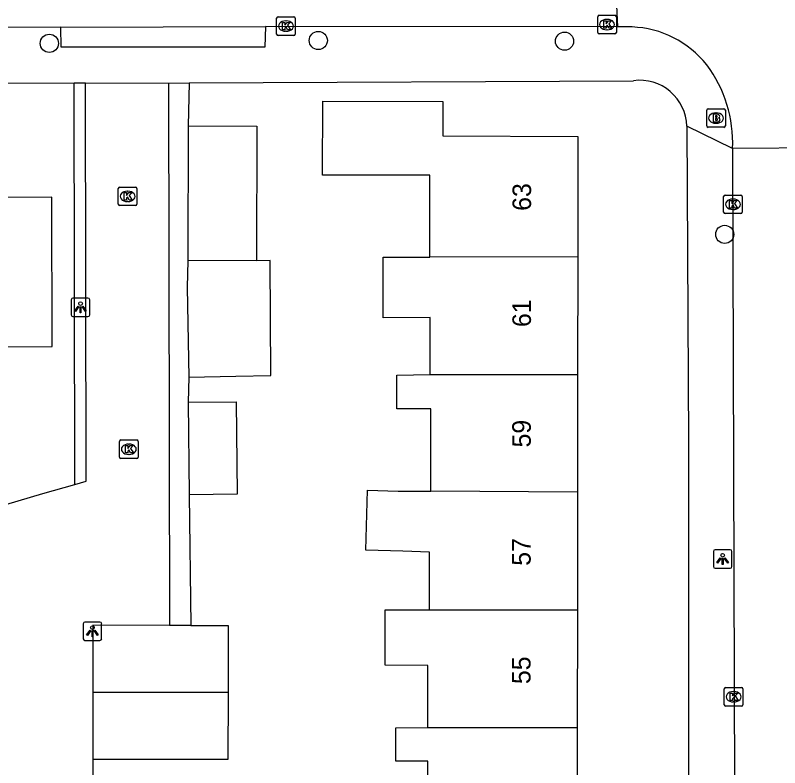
# Model space of a CAD drawing. Extents: x 160732 to 162105, y 387428 to 388479.
# Drawn here: x 161117.3 to 161158.48, y 388190.26 to 388230.78 of the extents above; entities that cross this region are included whole.
import ezdxf

# ---------------------------------------------------------------- set-up
doc = ezdxf.new("R2010")
doc.units = 0
for name, color, linetype in [('IMGEO_Boom', 7, 'Continuous'), ('IMGEO_Brandkraan', 7, 'Continuous'), ('IMGEO_Kolk', 7, 'Continuous'), ('IMGEO_Lichtpunt', 7, 'Continuous'), ('IMGEO_Muur', 7, 'Continuous'), ('IMGEO_Pand', 7, 'Continuous'), ('IMGEO_Pand_nummerreeks', 7, 'Continuous'), ('IMGEO_Rijbaan_lokaal_open', 7, 'Continuous'), ('IMGEO_Voetpad_open', 7, 'Continuous')]:
    doc.layers.add(name, color=color, linetype=linetype)

msp = doc.modelspace()

# ---------------------------------------------------------------- linework, layer by layer
at = {"layer": 'IMGEO_Boom'}
for centre in [(161119.136, 388229.271), (161133.623, 388229.425), (161146.891, 388229.388), (161155.522, 388218.983)]:
    msp.add_circle(centre, 0.489, dxfattribs=at)
at = {"layer": 'IMGEO_Brandkraan'}
for p, q in [((161154.554, 388224.823), (161154.554, 388225.675)), ((161154.629, 388225.749), (161155.481, 388225.749)), ((161155.555, 388225.675), (161155.555, 388224.823)), ((161155.042, 388225.529), (161155.067, 388225.529)), ((161155.065, 388224.969), (161155.04, 388224.969)), ((161155.481, 388224.749), (161154.629, 388224.749))]:
    msp.add_line(p, q, dxfattribs=at)
for points in [[(161154.554, 388224.823), (161154.554, 388225.675)], [(161154.629, 388225.749), (161155.481, 388225.749)], [(161155.555, 388225.675), (161155.555, 388224.823)], [(161154.902, 388225.449), (161154.902, 388225.049), (161155.115, 388225.049)], [(161155.133, 388225.449), (161154.902, 388225.449)], [(161155.081, 388225.368), (161155.027, 388225.368), (161155.027, 388225.292)], [(161155.027, 388225.292), (161155.08, 388225.292)], [(161155.089, 388225.216), (161155.027, 388225.216), (161155.027, 388225.135)], [(161155.027, 388225.135), (161155.089, 388225.135)], [(161155.481, 388224.749), (161154.629, 388224.749)]]:
    msp.add_lwpolyline(points, dxfattribs=at)
for centre, radius, start, end in [((161154.631, 388225.673), 0.0765, 91.552, 178.448), ((161154.631, 388225.673), 0.0765, 91.552, 178.448), ((161155.479, 388225.673), 0.0765, 1.552, 88.448), ((161155.479, 388225.673), 0.0765, 1.552, 88.448), ((161155.082, 388225.33), 0.0379, 267.8285, 90.9355), ((161155.09, 388225.175), 0.0404, 269.8759, 90.5077), ((161155.137, 388225.304), 0.145, 59.4692, 91.5367), ((161155.162, 388225.351), 0.0922, 285.5137, 58.1501), ((161155.167, 388225.159), 0.105, 301.3115, 78.989), ((161154.631, 388224.825), 0.0765, 181.552, 268.448), ((161154.631, 388224.825), 0.0765, 181.552, 268.448), ((161155.121, 388225.3), 0.251, 268.6676, 293.5347), ((161155.479, 388224.825), 0.0765, 271.552, 358.448), ((161155.479, 388224.825), 0.0765, 271.552, 358.448)]:
    msp.add_arc(centre, radius, start, end, dxfattribs=at)
for centre, major_axis, ratio, start_param, end_param in [((161155.041, 388225.249), (-0.387, 0.002), 0.722429, 4.712389, 7.853982), ((161155.066, 388225.249), (-0.39, 0.002), 0.717154, 1.570796, 4.712389)]:
    msp.add_ellipse(centre, major_axis=major_axis, ratio=ratio, start_param=start_param, end_param=end_param, dxfattribs=at)
at = {"layer": 'IMGEO_Kolk'}
for p, q in [((161131.38, 388229.773), (161131.38, 388230.625)), ((161131.455, 388230.699), (161132.307, 388230.699)), ((161132.381, 388230.625), (161132.381, 388229.773)), ((161148.682, 388229.856), (161148.682, 388230.708)), ((161148.757, 388230.782), (161149.609, 388230.782)), ((161149.17, 388230.562), (161149.195, 388230.562)), ((161149.683, 388230.708), (161149.683, 388229.856)), ((161131.868, 388230.479), (161131.893, 388230.479)), ((161131.891, 388229.919), (161131.866, 388229.919)), ((161149.609, 388229.782), (161148.757, 388229.782)), ((161149.193, 388230.002), (161149.168, 388230.002)), ((161132.307, 388229.699), (161131.455, 388229.699)), ((161122.926, 388221.531), (161123.778, 388221.531)), ((161122.851, 388220.605), (161122.851, 388221.457)), ((161123.339, 388221.311), (161123.364, 388221.311)), ((161123.852, 388221.457), (161123.852, 388220.605)), ((161155.537, 388221.103), (161156.389, 388221.103)), ((161123.362, 388220.751), (161123.337, 388220.751)), ((161155.462, 388220.177), (161155.462, 388221.029)), ((161155.95, 388220.883), (161155.975, 388220.883)), ((161156.463, 388221.029), (161156.463, 388220.177)), ((161123.778, 388220.531), (161122.926, 388220.531)), ((161155.973, 388220.323), (161155.948, 388220.323)), ((161156.389, 388220.103), (161155.537, 388220.103)), ((161122.992, 388207.911), (161123.844, 388207.911)), ((161122.917, 388206.985), (161122.917, 388207.837)), ((161123.405, 388207.691), (161123.43, 388207.691)), ((161123.918, 388207.837), (161123.918, 388206.985)), ((161123.428, 388207.131), (161123.403, 388207.131)), ((161123.844, 388206.911), (161122.992, 388206.911)), ((161155.497, 388193.654), (161155.497, 388194.506)), ((161155.572, 388194.58), (161156.424, 388194.58)), ((161155.985, 388194.36), (161156.01, 388194.36)), ((161156.498, 388194.506), (161156.498, 388193.654)), ((161156.424, 388193.58), (161155.572, 388193.58)), ((161156.008, 388193.8), (161155.983, 388193.8))]:
    msp.add_line(p, q, dxfattribs=at)
for points in [[(161131.38, 388229.773), (161131.38, 388230.625)], [(161131.455, 388230.699), (161132.307, 388230.699)], [(161132.381, 388230.625), (161132.381, 388229.773)], [(161148.682, 388229.856), (161148.682, 388230.708)], [(161148.757, 388230.782), (161149.609, 388230.782)], [(161149.683, 388230.708), (161149.683, 388229.856)], [(161131.701, 388230.399), (161131.824, 388230.399), (161131.824, 388230.248), (161131.954, 388230.399), (161132.118, 388230.399), (161131.972, 388230.248), (161132.125, 388229.999), (161131.973, 388229.999), (161131.888, 388230.163), (161131.824, 388230.096), (161131.824, 388229.999), (161131.701, 388229.999), (161131.701, 388230.399)], [(161149.003, 388230.482), (161149.126, 388230.482), (161149.126, 388230.331), (161149.256, 388230.482), (161149.42, 388230.482), (161149.274, 388230.331), (161149.427, 388230.082), (161149.275, 388230.082), (161149.19, 388230.246), (161149.126, 388230.179), (161149.126, 388230.082), (161149.003, 388230.082), (161149.003, 388230.482)], [(161149.609, 388229.782), (161148.757, 388229.782)], [(161132.307, 388229.699), (161131.455, 388229.699)], [(161122.926, 388221.531), (161123.778, 388221.531)], [(161122.851, 388220.605), (161122.851, 388221.457)], [(161123.172, 388221.231), (161123.295, 388221.231), (161123.295, 388221.08), (161123.425, 388221.231), (161123.589, 388221.231), (161123.443, 388221.08), (161123.596, 388220.831), (161123.444, 388220.831), (161123.359, 388220.995), (161123.295, 388220.928), (161123.295, 388220.831), (161123.172, 388220.831), (161123.172, 388221.231)], [(161123.852, 388221.457), (161123.852, 388220.605)], [(161155.537, 388221.103), (161156.389, 388221.103)], [(161155.462, 388220.177), (161155.462, 388221.029)], [(161155.783, 388220.803), (161155.906, 388220.803), (161155.906, 388220.652), (161156.036, 388220.803), (161156.2, 388220.803), (161156.054, 388220.652), (161156.207, 388220.403), (161156.055, 388220.403), (161155.97, 388220.567), (161155.906, 388220.5), (161155.906, 388220.403), (161155.783, 388220.403), (161155.783, 388220.803)], [(161156.463, 388221.029), (161156.463, 388220.177)], [(161123.778, 388220.531), (161122.926, 388220.531)], [(161156.389, 388220.103), (161155.537, 388220.103)], [(161122.992, 388207.911), (161123.844, 388207.911)], [(161122.917, 388206.985), (161122.917, 388207.837)], [(161123.238, 388207.611), (161123.361, 388207.611), (161123.361, 388207.46), (161123.491, 388207.611), (161123.655, 388207.611), (161123.509, 388207.46), (161123.662, 388207.211), (161123.51, 388207.211), (161123.425, 388207.375), (161123.361, 388207.308), (161123.361, 388207.211), (161123.238, 388207.211), (161123.238, 388207.611)], [(161123.918, 388207.837), (161123.918, 388206.985)], [(161123.844, 388206.911), (161122.992, 388206.911)], [(161155.497, 388193.654), (161155.497, 388194.506)], [(161155.572, 388194.58), (161156.424, 388194.58)], [(161156.498, 388194.506), (161156.498, 388193.654)], [(161155.818, 388194.28), (161155.941, 388194.28), (161155.941, 388194.129), (161156.071, 388194.28), (161156.235, 388194.28), (161156.089, 388194.129), (161156.242, 388193.88), (161156.09, 388193.88), (161156.005, 388194.044), (161155.941, 388193.977), (161155.941, 388193.88), (161155.818, 388193.88), (161155.818, 388194.28)], [(161156.424, 388193.58), (161155.572, 388193.58)]]:
    msp.add_lwpolyline(points, dxfattribs=at)
for centre, start, end in [((161131.457, 388230.623), 91.552, 178.448), ((161131.457, 388230.623), 91.552, 178.448), ((161132.305, 388230.623), 1.552, 88.448), ((161132.305, 388230.623), 1.552, 88.448), ((161148.759, 388230.706), 91.552, 178.448), ((161148.759, 388230.706), 91.552, 178.448), ((161149.607, 388230.706), 1.552, 88.448), ((161149.607, 388230.706), 1.552, 88.448), ((161131.457, 388229.775), 181.552, 268.448), ((161131.457, 388229.775), 181.552, 268.448), ((161132.305, 388229.775), 271.552, 358.448), ((161132.305, 388229.775), 271.552, 358.448), ((161148.759, 388229.858), 181.552, 268.448), ((161148.759, 388229.858), 181.552, 268.448), ((161149.607, 388229.858), 271.552, 358.448), ((161149.607, 388229.858), 271.552, 358.448), ((161122.928, 388221.455), 91.552, 178.448), ((161122.928, 388221.455), 91.552, 178.448), ((161123.776, 388221.455), 1.552, 88.448), ((161123.776, 388221.455), 1.552, 88.448), ((161155.539, 388221.027), 91.552, 178.448), ((161155.539, 388221.027), 91.552, 178.448), ((161156.387, 388221.027), 1.552, 88.448), ((161156.387, 388221.027), 1.552, 88.448), ((161122.928, 388220.607), 181.552, 268.448), ((161122.928, 388220.607), 181.552, 268.448), ((161123.776, 388220.607), 271.552, 358.448), ((161123.776, 388220.607), 271.552, 358.448), ((161155.539, 388220.179), 181.552, 268.448), ((161155.539, 388220.179), 181.552, 268.448), ((161156.387, 388220.179), 271.552, 358.448), ((161156.387, 388220.179), 271.552, 358.448), ((161122.994, 388207.835), 91.552, 178.448), ((161122.994, 388207.835), 91.552, 178.448), ((161123.842, 388207.835), 1.552, 88.448), ((161123.842, 388207.835), 1.552, 88.448), ((161122.994, 388206.987), 181.552, 268.448), ((161122.994, 388206.987), 181.552, 268.448), ((161123.842, 388206.987), 271.552, 358.448), ((161123.842, 388206.987), 271.552, 358.448), ((161155.574, 388194.504), 91.552, 178.448), ((161155.574, 388194.504), 91.552, 178.448), ((161156.422, 388194.504), 1.552, 88.448), ((161156.422, 388194.504), 1.552, 88.448), ((161155.574, 388193.656), 181.552, 268.448), ((161155.574, 388193.656), 181.552, 268.448), ((161156.422, 388193.656), 271.552, 358.448), ((161156.422, 388193.656), 271.552, 358.448)]:
    msp.add_arc(centre, 0.0765, start, end, dxfattribs=at)
for centre, major_axis, ratio, start_param, end_param in [((161149.169, 388230.282), (-0.387, 0.002), 0.722429, 4.712389, 7.853982), ((161149.194, 388230.282), (-0.39, 0.002), 0.717154, 1.570796, 4.712389), ((161131.867, 388230.199), (-0.387, 0.002), 0.722429, 4.712389, 7.853982), ((161131.892, 388230.199), (-0.39, 0.002), 0.717154, 1.570796, 4.712389), ((161123.338, 388221.031), (-0.387, 0.002), 0.722429, 4.712389, 7.853982), ((161123.363, 388221.031), (-0.39, 0.002), 0.717154, 1.570796, 4.712389), ((161155.949, 388220.603), (-0.387, 0.002), 0.722429, 4.712389, 7.853982), ((161155.974, 388220.603), (-0.39, 0.002), 0.717154, 1.570796, 4.712389), ((161123.404, 388207.411), (-0.387, 0.002), 0.722429, 4.712389, 7.853982), ((161123.429, 388207.411), (-0.39, 0.002), 0.717154, 1.570796, 4.712389), ((161155.984, 388194.08), (-0.387, 0.002), 0.722429, 4.712389, 7.853982), ((161156.009, 388194.08), (-0.39, 0.002), 0.717154, 1.570796, 4.712389)]:
    msp.add_ellipse(centre, major_axis=major_axis, ratio=ratio, start_param=start_param, end_param=end_param, dxfattribs=at)
at = {"layer": 'IMGEO_Lichtpunt'}
for p, q in [((161120.316, 388215.461), (161120.316, 388214.654)), ((161120.316, 388215.461), (161120.316, 388214.654)), ((161121.218, 388215.556), (161120.41, 388215.556)), ((161121.218, 388215.556), (161120.41, 388215.556)), ((161121.312, 388214.654), (161121.312, 388215.461)), ((161121.312, 388214.654), (161121.312, 388215.461)), ((161120.41, 388214.56), (161121.218, 388214.56)), ((161120.41, 388214.56), (161121.218, 388214.56)), ((161154.91, 388201.905), (161154.91, 388201.098)), ((161154.91, 388201.905), (161154.91, 388201.098)), ((161155.812, 388202), (161155.004, 388202)), ((161155.812, 388202), (161155.004, 388202)), ((161155.906, 388201.098), (161155.906, 388201.905)), ((161155.906, 388201.098), (161155.906, 388201.905)), ((161155.004, 388201.004), (161155.812, 388201.004)), ((161155.004, 388201.004), (161155.812, 388201.004)), ((161120.958, 388198.013), (161120.958, 388197.206)), ((161120.958, 388198.013), (161120.958, 388197.206)), ((161121.86, 388198.108), (161121.052, 388198.108)), ((161121.86, 388198.108), (161121.052, 388198.108)), ((161121.954, 388197.206), (161121.954, 388198.013)), ((161121.954, 388197.206), (161121.954, 388198.013)), ((161121.052, 388197.112), (161121.86, 388197.112)), ((161121.052, 388197.112), (161121.86, 388197.112))]:
    msp.add_line(p, q, dxfattribs=at)
for points in [[(161120.69, 388215.125), (161120.729, 388215.097), (161120.541, 388214.835), (161120.503, 388214.862), (161120.69, 388215.125)], [(161120.792, 388215.077), (161120.839, 388215.077), (161120.839, 388214.755), (161120.792, 388214.755), (161120.792, 388215.077)], [(161120.902, 388215.097), (161120.94, 388215.124), (161121.127, 388214.862), (161121.088, 388214.834), (161120.902, 388215.097)], [(161155.284, 388201.569), (161155.323, 388201.541), (161155.135, 388201.279), (161155.097, 388201.306), (161155.284, 388201.569)], [(161155.386, 388201.521), (161155.433, 388201.521), (161155.433, 388201.199), (161155.386, 388201.199), (161155.386, 388201.521)], [(161155.496, 388201.541), (161155.534, 388201.568), (161155.721, 388201.306), (161155.682, 388201.278), (161155.496, 388201.541)], [(161121.332, 388197.677), (161121.371, 388197.649), (161121.183, 388197.387), (161121.145, 388197.414), (161121.332, 388197.677)], [(161121.434, 388197.629), (161121.481, 388197.629), (161121.481, 388197.307), (161121.434, 388197.307), (161121.434, 388197.629)], [(161121.544, 388197.649), (161121.582, 388197.676), (161121.769, 388197.414), (161121.73, 388197.386), (161121.544, 388197.649)]]:
    msp.add_lwpolyline(points, dxfattribs=at)
for centre in [(161120.815, 388215.259), (161155.409, 388201.703), (161121.457, 388197.811)]:
    msp.add_circle(centre, 0.0994, dxfattribs=at)
for centre, start, end in [((161120.41, 388215.461), 90, 180), ((161120.41, 388215.461), 90, 180), ((161121.218, 388215.461), 0, 90), ((161121.218, 388215.461), 0, 90), ((161120.41, 388214.654), 180, 270), ((161120.41, 388214.654), 180, 270), ((161121.218, 388214.654), 270, 0), ((161121.218, 388214.654), 270, 360), ((161155.004, 388201.905), 90, 180), ((161155.004, 388201.905), 90, 180), ((161155.812, 388201.905), 0, 90), ((161155.812, 388201.905), 0, 90), ((161155.004, 388201.098), 180, 270), ((161155.004, 388201.098), 180, 270), ((161155.812, 388201.098), 270, 0), ((161155.812, 388201.098), 270, 360), ((161121.052, 388198.013), 90, 180), ((161121.052, 388198.013), 90, 180), ((161121.86, 388198.013), 0, 90), ((161121.86, 388198.013), 0, 90), ((161121.052, 388197.206), 180, 270), ((161121.052, 388197.206), 180, 270), ((161121.86, 388197.206), 270, 0), ((161121.86, 388197.206), 270, 360)]:
    msp.add_arc(centre, 0.0946, start, end, dxfattribs=at)
at = {"layer": 'IMGEO_Muur'}
msp.add_lwpolyline([(161126.67, 388204.965), (161126.762, 388197.927)], dxfattribs=at)
at = {"layer": 'IMGEO_Pand'}
for points in [[(161112.664, 388212.927), (161114.29, 388212.928), (161119.289, 388212.942), (161119.266, 388220.98), (161115.604, 388220.969), (161115.589, 388226.181), (161112.63, 388226.173)], [(161139.632, 388217.761), (161139.632, 388222.181), (161137.767, 388222.181), (161137.667, 388222.181), (161133.855, 388222.181), (161133.869, 388226.152), (161140.342, 388226.131), (161140.336, 388224.285), (161147.612, 388224.26), (161147.605, 388217.772)], [(161126.617, 388224.824), (161126.596, 388217.575)], [(161126.617, 388224.824), (161130.322, 388224.814), (161130.301, 388217.565)], [(161147.605, 388217.772), (161139.632, 388217.761)], [(161147.605, 388217.772), (161147.597, 388211.434)], [(161126.596, 388217.575), (161126.557, 388216.125), (161126.659, 388211.29)], [(161130.301, 388217.565), (161126.596, 388217.575)], [(161126.659, 388211.29), (161129.19, 388211.343), (161131.073, 388211.382), (161131.028, 388217.571), (161130.301, 388217.565)], [(161139.649, 388211.443), (161139.649, 388214.501), (161137.119, 388214.498), (161137.115, 388217.758), (161139.632, 388217.761)], [(161139.681, 388205.153), (161139.681, 388209.591), (161137.86, 388209.591), (161137.86, 388211.406), (161139.649, 388211.443)], [(161139.649, 388211.443), (161147.597, 388211.434)], [(161147.597, 388211.434), (161147.59, 388205.096)], [(161126.606, 388209.94), (161129.195, 388209.973), (161129.259, 388204.999), (161126.67, 388204.965)], [(161126.606, 388209.94), (161126.67, 388204.965)], [(161139.609, 388198.768), (161139.61, 388199.021), (161139.613, 388199.643), (161139.622, 388201.876), (161138.185, 388201.917), (161136.188, 388201.974), (161136.279, 388205.2), (161137.931, 388205.153), (161139.681, 388205.153)], [(161147.59, 388205.096), (161139.681, 388205.153)], [(161147.59, 388205.096), (161147.583, 388198.758)], [(161139.531, 388192.418), (161139.529, 388195.773), (161137.221, 388195.776), (161137.225, 388198.771), (161137.756, 388198.77), (161139.609, 388198.768)], [(161139.609, 388198.768), (161147.583, 388198.758)], [(161147.583, 388198.758), (161147.576, 388192.42)], [(161125.617, 388197.928), (161121.484, 388197.931), (161121.482, 388194.318)], [(161126.762, 388197.927), (161125.806, 388197.928), (161125.617, 388197.928)], [(161126.762, 388197.927), (161128.764, 388197.926), (161128.762, 388194.312)], [(161121.482, 388194.318), (161121.48, 388190.706)], [(161128.762, 388194.312), (161128.76, 388190.702), (161121.48, 388190.706)], [(161128.762, 388194.312), (161121.482, 388194.318)], [(161139.527, 388186.125), (161139.524, 388190.619), (161137.802, 388190.617), (161137.801, 388192.417), (161139.531, 388192.418)], [(161139.531, 388192.418), (161147.576, 388192.42)], [(161147.576, 388192.42), (161147.569, 388186.082)]]:
    msp.add_lwpolyline(points, dxfattribs=at)
at = {"layer": 'IMGEO_Rijbaan_lokaal_open'}
for points in [[(161149.51, 388235.15), (161149.736, 388230.154)], [(161119.757, 388230.149), (161075.503, 388230.076)], [(161119.757, 388230.149), (161130.785, 388230.186)], [(161149.736, 388230.154), (161130.785, 388230.186)], [(161150.532, 388230.153), (161149.736, 388230.154)], [(161120.504, 388205.518), (161121.114, 388205.701), (161121.078, 388227.145)], [(161121.078, 388227.145), (161125.564, 388227.132)], [(161125.564, 388227.132), (161125.617, 388197.928)], [(161160.943, 388223.645), (161155.942, 388223.612)], [(161155.942, 388223.612), (161156.12, 388166.254)], [(161105.3, 388201.027), (161118.777, 388205.02), (161120.504, 388205.518)], [(161121.48, 388190.706), (161121.484, 388189.17)]]:
    msp.add_lwpolyline(points, dxfattribs=at)
for centre, radius, start, end in [((161150.328, 388224.766), 5.391, 38.3929, 87.829), ((161149.017, 388223.941), 6.932, 357.281, 37.0121)]:
    msp.add_arc(centre, radius, start, end, dxfattribs=at)
at = {"layer": 'IMGEO_Voetpad_open'}
for points in [[(161130.785, 388230.186), (161130.748, 388229.063), (161119.777, 388229.065), (161119.757, 388230.149)], [(161126.663, 388227.137), (161150.612, 388227.261)], [(161074.571, 388221.102), (161074.599, 388226.989), (161120.471, 388227.138)], [(161120.471, 388227.138), (161121.078, 388227.145)], [(161120.504, 388205.518), (161120.471, 388227.138)], [(161125.564, 388227.132), (161126.663, 388227.137)], [(161126.663, 388227.137), (161126.617, 388224.824)], [(161153.48, 388224.813), (161153.568, 388207.782), (161153.588, 388170.261), (161153.606, 388166.499)], [(161155.942, 388223.612), (161153.48, 388224.813)], [(161126.659, 388211.29), (161126.606, 388209.94)], [(161126.67, 388204.965), (161126.762, 388197.927)]]:
    msp.add_lwpolyline(points, dxfattribs=at)
msp.add_arc((161150.941, 388224.742), 2.54, 1.6053, 97.4295, dxfattribs=at)

# ---------------------------------------------------------------- texts
at = {"layer": 'IMGEO_Pand_nummerreeks'}
for s, rotation, p in [('63', 89.9351, (161145.087, 388220.251)), ('61', 89.9372, (161145.081, 388213.992)), ('59', 89.9351, (161145.073, 388207.508)), ('57', 89.9372, (161145.066, 388201.136)), ('55', 89.9372, (161145.059, 388194.764))]:
    msp.add_text(s, height=1, rotation=rotation, dxfattribs=at).set_placement(p)

doc.saveas('drawing.dxf')
